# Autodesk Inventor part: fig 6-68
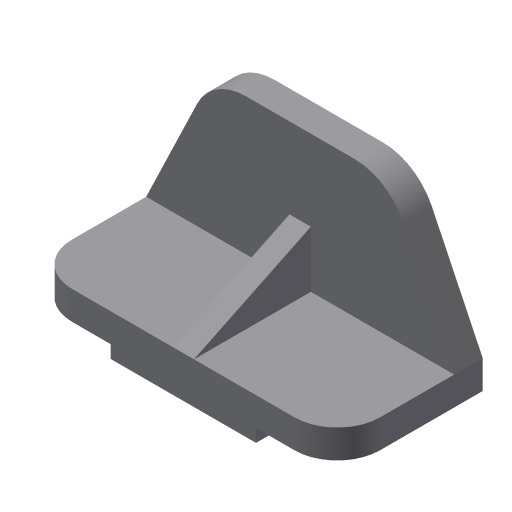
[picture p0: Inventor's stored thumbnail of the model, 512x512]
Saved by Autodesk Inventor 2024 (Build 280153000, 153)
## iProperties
Shininess: 77.0
Length Units: 11269
Angle Units: 11279
Time Units: 11290
Mass Units: 11283
Length Display Precision: 3
Angle Display Precision: 2
Created: 2001-12
Part Number: fig 6-68
Document SubType Name: Modeling
Designer: Renu Muthoo
Density: 1 g/cm^3
Material: Generic
Appearance: Default
Density: 0.0
Volumn: 0.0
Area: 0.0
PropertySet Name: Model Information
Control State: 0
Master: False
Checked Out: False
Author: Renu Muthoo
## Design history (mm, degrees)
sketch "Sketch2"
  geometry: L1 (-67.219, 19.116)-(148.781, 19.116); L2 (148.781, 19.116)-(148.781, -0.884); L3 (-67.219, -0.884)-(-67.219, 19.116); L4 (-10.219, -0.884)-(-10.219, -9.884); L5 (-10.219, -9.884)-(91.781, -9.884); L6 (91.781, -9.884)-(91.781, -0.884); L7 (148.781, -0.884)-(91.781, -0.884); L8 (-10.219, -0.884)-(-67.219, -0.884)
  constraints: 16 end point, 5 parallel, 4 perpendicular, 2 equal length, 1 horizontal
  dimensions: "d0" = 102 distance of L4.end L5.end; "d1" = 57 distance of L4.start L3.start; "d2" = 29 distance between parallel lines of L1 L5; "d3" = 20 distance of L1.end L2.end
extrude "Extrusion1" new body sketch "Sketch2" distance "d4" = 102; taper "d5" = 0 deg
sketch "Sketch3"
  geometry: L1 (67.219, -19.116)-(-148.781, -19.116) reference; L2 (67.219, -19.116)-(31.475, -93.564); L3 (-2.781, -115.116)-(-78.781, -115.116); L4 (-113.038, -93.564)-(-148.781, -19.116); A1 r 38 centre (-2.781, -77.116) between (-2.781, -115.116) and (31.475, -93.564); A2 r 38 centre (-78.781, -77.116) between (-113.038, -93.564) and (-78.781, -115.116)
  constraints: 6 end point, 4 point on circle, 4 tangent, 2 centre point, 1 equal length, 1 equal radius, 1 parallel
  dimensions: "d6" = 96 distance between parallel lines of L3 L1; "d7" = 38 radius of A1; "d8" = 76 distance of A2.centre A1.centre
extrude "Extrusion2" join sketch "Sketch3" distance "d9" = 20; taper "d10" = 0 deg
fillet "Fillet1" dims "d11" = 30
workplane "Work Plane1"
sketch "Sketch7"
  geometry: L1 (0, -82)-(-39.557, 0)
  constraints: 2 end point
feature "Rib4" sketch "Sketch7" dims "d37" = 1, "d38" = 15, "d39" = 0
body "Solid1"
node "Sketch1"
other parameters: "d12" = -108
